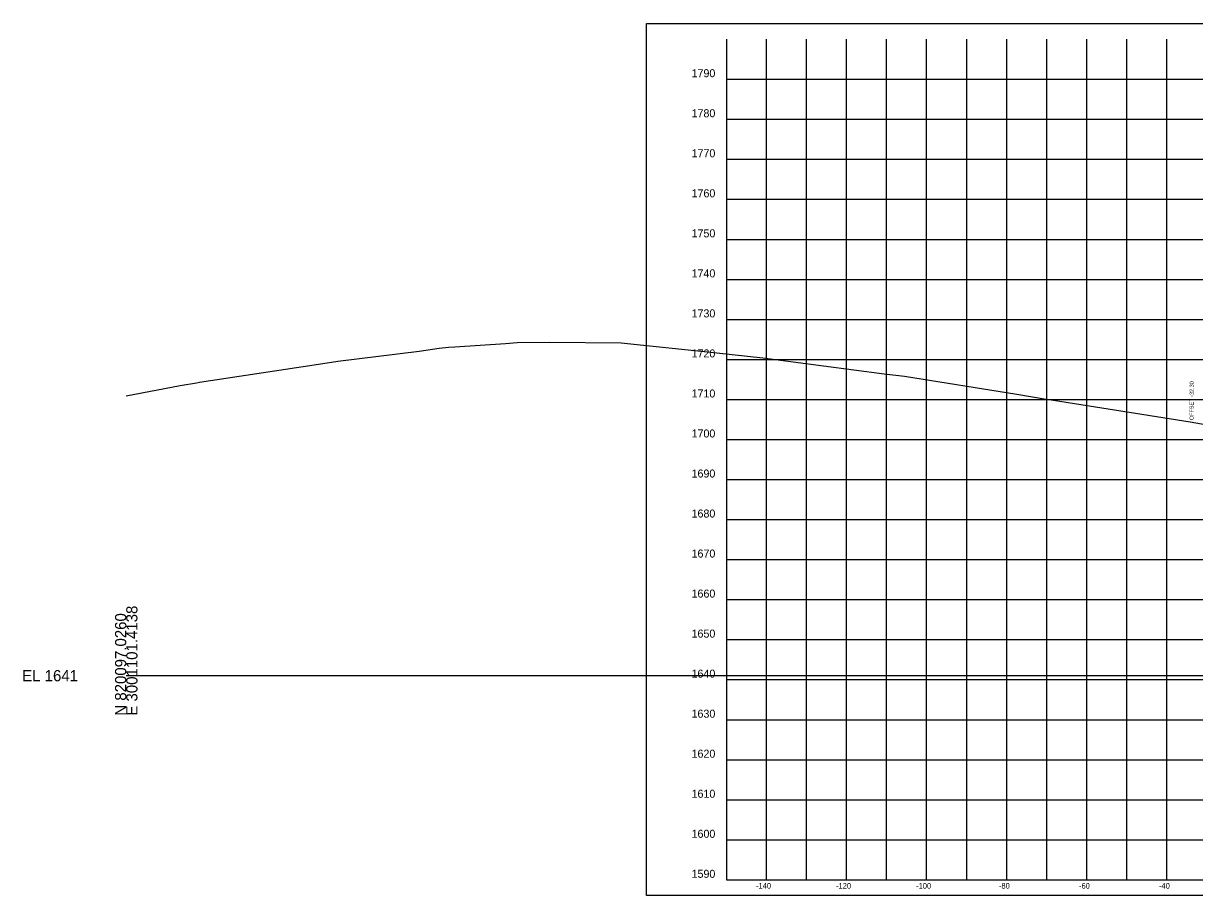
# Model space of a CAD drawing. Extents: x -26 to 603, y -61 to 1770.
# Drawn here: x -25.7 to 266.9, y 945.1 to 1162.9 of the extents above; entities that cross this region are included whole.
import ezdxf

# ---------------------------------------------------------------- set-up
doc = ezdxf.new("R2010")
doc.units = 0
for name, color, linetype in [('DESIGN - SHEET - Corner Text', 7, 'Continuous'), ('DESIGN - SHEET - Light Grid', 7, 'Continuous'), ('DESIGN - SHEET - Linework', 7, 'Continuous'), ('DESIGN - SHEET - Plot Shape', 7, 'Continuous'), ('DESIGN - TYPICAL - Slope Tie Text', 7, 'Continuous'), ('SURVEY - GROUND - Top of Ground', 7, 'Continuous')]:
    doc.layers.add(name, color=color, linetype=linetype)

msp = doc.modelspace()

# ---------------------------------------------------------------- linework, layer by layer
at = {"layer": 'DESIGN - SHEET - Light Grid'}
msp.add_line((0, 1000), (300, 1000), dxfattribs=at)
at = {"layer": 'DESIGN - SHEET - Linework'}
for p, q in [((160, 949), (160, 1159)), ((170, 949), (170, 1159)), ((180, 949), (180, 1159)), ((190, 949), (190, 1159)), ((200, 949), (200, 1159)), ((210, 949), (210, 1159)), ((220, 949), (220, 1159)), ((230, 949), (230, 1159)), ((240, 949), (240, 1159)), ((250, 949), (250, 1159)), ((260, 949), (260, 1159)), ((150, 1149), (450, 1149)), ((150, 1139), (450, 1139)), ((150, 1129), (450, 1129)), ((150, 1119), (450, 1119)), ((150, 1109), (450, 1109)), ((150, 1099), (450, 1099)), ((150, 1089), (450, 1089)), ((150, 1079), (450, 1079)), ((150, 1069), (450, 1069)), ((150, 1059), (450, 1059)), ((150, 1049), (450, 1049)), ((150, 1039), (450, 1039)), ((150, 1029), (450, 1029)), ((150, 1019), (450, 1019)), ((150, 1009), (450, 1009)), ((150, 999), (450, 999)), ((150, 989), (450, 989)), ((150, 979), (450, 979)), ((150, 969), (450, 969)), ((150, 959), (450, 959))]:
    msp.add_line(p, q, dxfattribs=at)
msp.add_lwpolyline([(150, 1159), (150, 949), (450, 949), (450, 1159)], dxfattribs=at)
at = {"layer": 'DESIGN - SHEET - Plot Shape'}
msp.add_lwpolyline([(130, 1162.94), (470, 1162.94), (470, 945.06), (130, 945.06)], close=True, dxfattribs=at)
at = {"layer": 'SURVEY - GROUND - Top of Ground'}
msp.add_lwpolyline([(0, 1069.92), (13.46, 1072.49), (17.53, 1073.19), (18.3, 1073.33), (46.92, 1077.68), (52.86, 1078.57), (73.18, 1081.1), (78.19, 1081.83), (80.55, 1082.07), (82.07, 1082.15), (94.79, 1083), (97.68, 1083.27), (105.73, 1083.28), (123.68, 1083.15), (147.6, 1080.65), (159.08, 1079.43), (189.41, 1075.41), (194.49, 1074.78), (222.57, 1070.32), (229.9, 1069.11), (231.68, 1068.84), (265.88, 1063.38), (271.49, 1062.39)], dxfattribs=at)

# ---------------------------------------------------------------- texts
at = {"layer": 'DESIGN - SHEET - Corner Text'}
for s, height, p in [('1790', 2, (141.25, 1149.5)), ('1780', 2, (141.25, 1139.5)), ('1770', 2, (141.25, 1129.5)), ('1760', 2, (141.25, 1119.5)), ('1750', 2, (141.25, 1109.5)), ('1740', 2, (141.25, 1099.5)), ('1730', 2, (141.25, 1089.5)), ('1720', 2, (141.25, 1079.5)), ('1710', 2, (141.25, 1069.5)), ('1700', 2, (141.25, 1059.5)), ('1690', 2, (141.25, 1049.5)), ('1680', 2, (141.25, 1039.5)), ('1670', 2, (141.25, 1029.5)), ('1660', 2, (141.25, 1019.5)), ('1650', 2, (141.25, 1009.5)), ('1640', 2, (141.25, 999.5)), ('1630', 2, (141.25, 989.5)), ('1620', 2, (141.25, 979.5)), ('1610', 2, (141.25, 969.5)), ('1600', 2, (141.25, 959.5)), ('1590', 2, (141.25, 949.5)), ('-140', 1.4, (157.37, 946.8)), ('-120', 1.4, (177.37, 946.8)), ('-100', 1.4, (197.37, 946.8)), ('-80', 1.4, (218.06, 946.8)), ('-60', 1.4, (238.06, 946.8)), ('-40', 1.4, (258.06, 946.8))]:
    msp.add_text(s, height=height, dxfattribs=at).set_placement(p)
at = {"layer": 'DESIGN - SHEET - Light Grid'}
for s, p in [('N 820097.0260', (0, 990)), ('E 3001101.4138', (2.8, 990))]:
    msp.add_text(s, height=2.8, rotation=90, dxfattribs=at).set_placement(p)
msp.add_text('EL 1641', height=2.8, dxfattribs=at).set_placement((-26, 998.6))
at = {"layer": 'DESIGN - TYPICAL - Slope Tie Text'}
msp.add_text('OFFSET -32.30', height=1, rotation=90, dxfattribs=at).set_placement((266.7, 1063.81))

doc.saveas('drawing.dxf')
